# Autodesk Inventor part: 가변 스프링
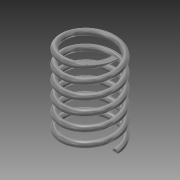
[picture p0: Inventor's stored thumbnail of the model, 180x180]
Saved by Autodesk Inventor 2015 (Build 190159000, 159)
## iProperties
Created: 2015-10
Part Number: 가변 스프링
Material: Steel, Mild
Document SubType Name: Modeling
Designer: youjin19
Density: 7.85 g/cm^3
Appearance: Semi-Polished
Mass: 128.859 g
Surface Area: 133.055 cm^2
Volume: 16.4151 cm^3
Author: youjin19
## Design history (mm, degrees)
sketch "Sketch1"
  geometry: L1 (0, 0)-(-22.5, 0); L2 (-22.5, 0)-(-22.5, 73.25); L3 (-22.5, 73.25)-(0, 73.25); L4 (0, 73.25)-(0, 0); C1 r 2.5 at (-22.5, 0)
  constraints: 8 end point, 2 parallel, 1 centre point, 1 coincident, 1 horizontal, 1 perpendicular
  dimensions: "d0" = 73.25 distance between parallel lines of L1 L3 (derived); "d1" = 45 diameter of L2 L4; "d2" = 5 diameter of C1
coil "Coil1" sketch "Sketch1" pitch "d3" = 10; turns "d5" = 6; dims "d4" = 73.25 (= d0), "d6" = 0, angle "d7" = 90 deg, angle "d8" = 90 deg, "d9" = 0, "d10" = 0
sketch "Sketch2"
  geometry: L1 (25, 0)-(20, 0) reference; 1 further point
  constraints: 1 horizontal alignment
extrude "Extrusion1" cut sketch "Sketch2" stored distance "d11" = 10; taper "d12" = 0 deg
workplane "Work Plane1"
sketch "Sketch3"
  geometry: L1 (-25, 0)-(-20, 0) reference; 1 further point
  constraints: 1 horizontal alignment
extrude "Extrusion2" cut sketch "Sketch3" stored distance "d13" = 10; taper "d14" = 0 deg
body "Solid1"
node "Project Cut Edges1"
node "Project Cut Edges2"
